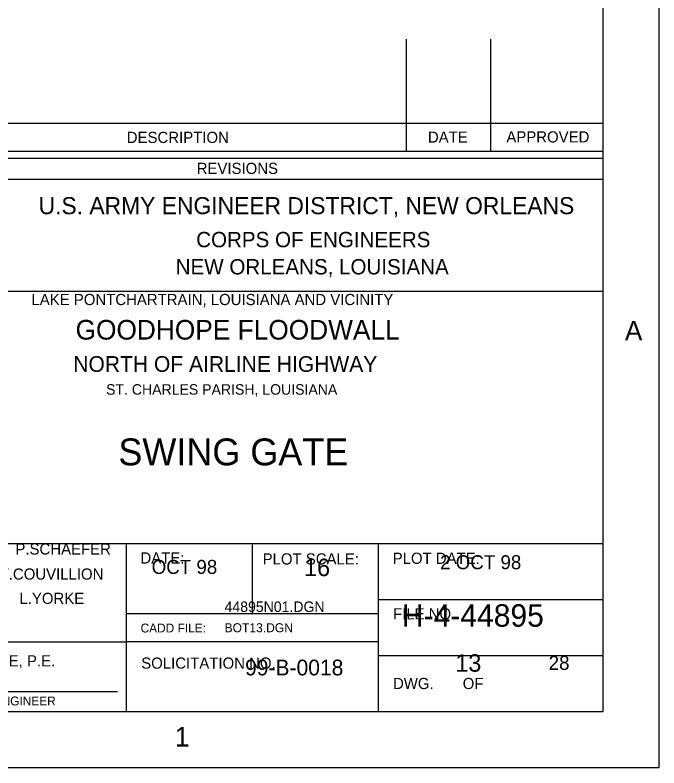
# Model space of a CAD drawing. Extents: x 0 to 53.3, y -0.3 to 37.1.
# Drawn here: x 45.68 to 53.33, y -0.25 to 8.71 of the extents above; entities that cross this region are included whole.
import ezdxf

# ---------------------------------------------------------------- set-up
doc = ezdxf.new("R2010")
doc.units = 0
doc.layers.add('Level 1', color=7, linetype='Continuous')
doc.layers.add('Level 2', color=7, linetype='Continuous')

msp = doc.modelspace()

# ---------------------------------------------------------------- linework, layer by layer
at = {"layer": 'Level 1'}
for p, q in [((50.3333, 7.0833), (50.3333, 8.4167)), ((51.3333, 7.0833), (51.3333, 8.4167)), ((52.6667, 7.4167), (44, 7.4167)), ((52.6667, 7.0833), (44, 7.0833)), ((52.6667, 7), (44, 7)), ((52.6667, 6.75), (44, 6.75)), ((52.6667, 5.4167), (44, 5.4167)), ((52.6667, 2.4167), (44, 2.4167)), ((47, 0.4167), (47, 2.4167)), ((48.5, 1.5833), (48.5, 2.4167)), ((50, 0.4167), (50, 2.4167)), ((52.6667, 1.75), (50, 1.75)), ((50, 1.5833), (47, 1.5833)), ((44, 1.25), (47, 1.25)), ((50, 1.25), (47, 1.25)), ((52.6667, 1.0833), (50, 1.0833)), ((44.0897, 0.6612), (46.8937, 0.6612))]:
    msp.add_line(p, q, dxfattribs=at)
for points in [[(0, 37.0833), (53.3333, 37.0833), (53.3333, -0.25), (0, -0.25)], [(2, 36.4167), (52.6667, 36.4167), (52.6667, 0.4167), (2, 0.4167)]]:
    msp.add_lwpolyline(points, close=True, dxfattribs=at)

# ---------------------------------------------------------------- texts
for s, height, p in [('DESCRIPTION', 0.132833, (47.0053, 7.1838)), ('DATE', 0.13283, (50.586, 7.187)), ('APPROVED', 0.13283, (51.519, 7.1898)), ('REVISIONS', 0.13283, (47.8365, 6.8153)), ('U.S. ARMY ENGINEER DISTRICT, NEW ORLEANS', 0.203167, (45.9565, 6.337)), ('CORPS OF ENGINEERS', 0.18285, (47.8307, 5.9432)), ('NEW ORLEANS, LOUISIANA', 0.18285, (47.5867, 5.62)), ('A', 0.2337, (52.9283, 4.8345)), ('DATE:', 0.13283, (47.1678, 2.1817)), ('PLOT SCALE:', 0.132833, (48.6208, 2.17)), ('PLOT DATE:', 0.13283, (50.1673, 2.1777)), ('FILE NO.', 0.13283, (50.171, 1.5168)), ('CADD FILE:', 0.10567, (47.1692, 1.3613)), ('SOLICITATION NO.', 0.132833, (47.177, 0.9308)), ('DWG.       OF', 0.132833, (50.171, 0.6882)), ('DESIGN ENGINEER', 0.105667, (44.8413, 0.4937)), ('1', 0.2337, (47.5767, 0.0048))]:
    msp.add_text(s, height=height, dxfattribs=at).set_placement(p)
at = {"layer": 'Level 2'}
for s, height, p in [('LAKE PONTCHARTRAIN, LOUISIANA AND VICINITY', 0.132833, (45.8718, 5.2555)), ('GOODHOPE FLOODWALL', 0.233667, (46.3962, 4.8452)), ('NORTH OF AIRLINE HIGHWAY', 0.187167, (46.3688, 4.4613)), ('ST. CHARLES PARISH, LOUISIANA', 0.125, (46.7593, 4.1897)), ('SWING GATE', 0.32006, (46.9054, 3.3493)), ('P.SCHAEFER', 0.13283, (45.6811, 2.2882)), ('16', 0.20833, (49.1127, 2.0312)), ('2 OCT 98', 0.16667, (50.7308, 2.1138)), ('OCT 98', 0.16667, (47.301, 2.0578)), ('V.COUVILLION', 0.132833, (45.4835, 1.99)), ('L.YORKE', 0.13283, (45.729, 1.7007)), ('44895N01.DGN', 0.125, (48.1683, 1.6052)), ('H-4-44895', 0.26717, (50.2767, 1.4298)), ('BOT13.DGN', 0.10717, (48.1683, 1.364)), ('L. W. YORKE, P.E.', 0.132833, (44.634, 0.9576)), ('13', 0.20833, (50.9117, 0.8942)), ('28', 0.16667, (52.0218, 0.9165)), ('99-B-0018', 0.18717, (48.4118, 0.8508))]:
    msp.add_text(s, height=height, dxfattribs=at).set_placement(p)

doc.saveas('drawing.dxf')
